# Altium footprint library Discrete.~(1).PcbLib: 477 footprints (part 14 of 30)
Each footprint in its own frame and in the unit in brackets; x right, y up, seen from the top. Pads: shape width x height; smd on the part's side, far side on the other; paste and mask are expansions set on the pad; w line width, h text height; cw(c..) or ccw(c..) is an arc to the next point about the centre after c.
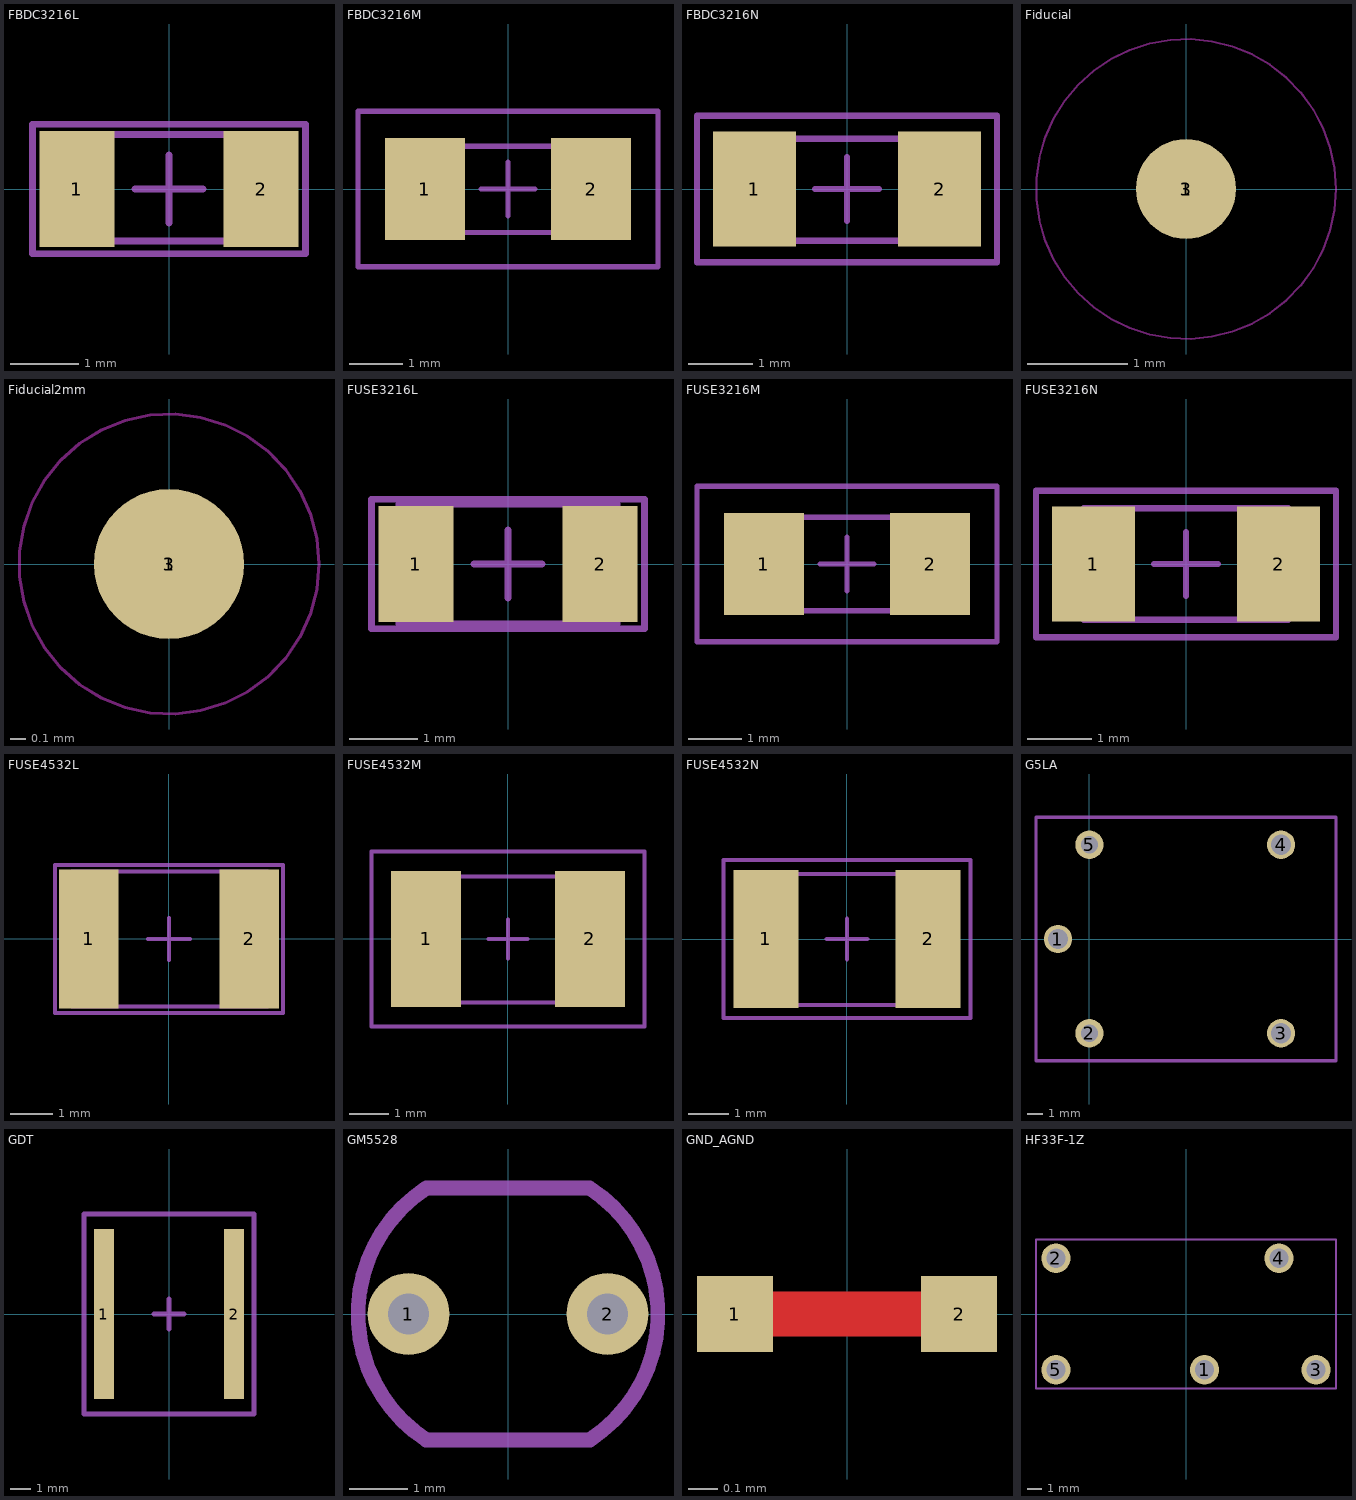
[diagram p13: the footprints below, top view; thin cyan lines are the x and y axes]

## FBDC3216L [mm] "Ferrite Bead, Body 3.2x1.6mm, IPC High Density"
height 0.71
pads (2):
  rect 1.1x1.7 smd: 1(-1.35,0) 2(1.35,0)
Mechanical 13:
  lines w0.1: -1.6,-0.762 -1.6,0.8 1.6,0.8 1.6,-0.762 -1.6,-0.762
Mechanical 15:
  lines w0.1: -0.5,0 0.5,0 ; 0,-0.5 0,0.5 ; -2,-0.95 -2,0.95 2,0.95 2,-0.95 -2,-0.95
3D body "User Library-ind_1206.STEP": height 1.1, standoff 0, extent -1.6,-0.8 1.6,0.8

## FBDC3216M [mm] "Ferrite Bead, Body 3.2x1.6mm, IPC Low Density"
height 0.71
pads (2):
  rect 1.5x1.9 smd: 1(-1.55,0) 2(1.55,0)
Mechanical 13:
  lines w0.1: -1.6,-0.813 -1.6,0.8 -1.587,0.799 0.837,0.799 1.601,0.799 1.601,-0.813 -1.6,-0.813
Mechanical 15:
  lines w0.1: -0.5,0 0.5,0 ; 0,-0.5 0,0.5 ; -2.8,-1.45 -2.8,1.45 2.8,1.45 2.8,-1.45 -2.8,-1.45
3D body "User Library-ind_1206.STEP": height 1.1, standoff 0, extent -1.6,-0.8 1.6,0.8

## FBDC3216N [mm] "Ferrite Bead, Body 3.2x1.6mm, IPC Medium Density"
height 0.71
pads (2):
  rect 1.3x1.8 smd: 1(-1.45,0) 2(1.45,0)
Mechanical 13:
  lines w0.1: -1.6,-0.813 -1.6,0.787 1.6,0.787 1.6,-0.813 -1.6,-0.813
Mechanical 15:
  lines w0.1: -0.5,0 0.5,0 ; 0,-0.5 0,0.5 ; -2.35,-1.15 -2.35,1.15 2.35,1.15 2.35,-1.15 -2.35,-1.15
3D body "User Library-ind_1206.STEP": height 1.1, standoff 0, extent -1.6,-0.8 1.6,0.8

## Fiducial [mm]
pads (2):
  round 1 smd: 1(0,0)
  round 3 on Top Solder: 3(0,0)
Top Layer keep-out:
  circle w0.02: c0,0 r1.5

## Fiducial2mm [mm]
pads (2):
  round 1 smd: 1(0,0)
  round 2 on Top Solder: 3(0,0)
Top Layer keep-out:
  circle w0.02: c0,0 r1

## FUSE3216L [mm] "Fuse, Body 3.2x1.6mm, IPC High Density"
height 0.71
pads (2):
  rect 1.1x1.7 smd: 1(-1.35,0) 2(1.35,0)
Mechanical 13:
  lines w0.1: -1.601,-0.875 1.601,-0.875 1.601,0.875 -1.601,0.875 -1.601,-0.875
Mechanical 15:
  lines w0.1: -0.5,0 0.5,0 ; 0,-0.5 0,0.5 ; -2,-0.95 2,-0.95 2,0.95 -2,0.95 -2,-0.95
3D body "User Library-nona SMD075F.STEP": height 0.56, standoff 0, extent -1.601,-0.826 1.601,0.826

## FUSE3216M [mm] "Fuse, Body 3.2x1.6mm, IPC Low Density"
height 0.71
pads (2):
  rect 1.5x1.9 smd: 1(-1.55,0) 2(1.55,0)
Mechanical 13:
  lines w0.1: -1.601,-0.875 -1.601,0.875 1.601,0.875 1.601,-0.875 -1.601,-0.875
Mechanical 15:
  lines w0.1: -0.5,0 0.5,0 ; 0,-0.5 0,0.5 ; -2.8,-1.45 -2.8,1.45 2.8,1.45 2.8,-1.45 -2.8,-1.45
3D body "User Library-nona SMD075F.STEP": height 0.56, standoff 0, extent -1.601,-0.826 1.601,0.826

## FUSE3216N [mm] "Fuse, Body 3.2x1.6mm, IPC Medium Density"
height 0.71
pads (2):
  rect 1.3x1.8 smd: 1(-1.45,0) 2(1.45,0)
Mechanical 13:
  lines w0.1: -1.601,-0.875 -1.601,0.875 1.601,0.875 1.601,-0.875 -1.601,-0.875
Mechanical 15:
  lines w0.1: -0.5,0 0.5,0 ; 0,-0.5 0,0.5 ; -2.35,-1.15 -2.35,1.15 2.35,1.15 2.35,-1.15 -2.35,-1.15
3D body "User Library-nona SMD075F.STEP": height 0.56, standoff 0, extent -1.601,-0.826 1.601,0.826

## FUSE4532L [mm]
height 0.71
pads (2):
  rect 1.4x3.3 smd: 1(-1.9,0) 2(1.9,0)
Mechanical 13:
  lines w0.1: -2.298,-1.598 -2.298,1.597 2.337,1.597 2.337,-1.598 -2.298,-1.598
Mechanical 15:
  lines w0.1: -0.5,0 0.5,0 ; 0,-0.5 0,0.5 ; -2.7,-1.75 -2.7,1.75 2.7,1.75 2.7,-1.75 -2.7,-1.75
3D body "FU 01812.STEP": height 0.87, standoff 0, extent -2.3,-1.61 2.3,1.61

## FUSE4532M [mm]
height 0.71
pads (2):
  rect 1.8x3.5 smd: 1(-2.1,0) 2(2.1,0)
Mechanical 13:
  lines w0.1: -2.311,-1.626 -2.311,1.6 2.311,1.6 2.311,-1.626 -2.311,-1.626
Mechanical 15:
  lines w0.1: -0.5,0 0.5,0 ; 0,-0.5 0,0.5 ; -3.5,-2.25 -3.5,2.25 3.5,2.25 3.5,-2.25 -3.5,-2.25
3D body "FU 01812.STEP": height 0.87, standoff 0, extent -2.3,-1.61 2.3,1.61

## FUSE4532N [mm]
height 0.71
pads (2):
  rect 1.6x3.4 smd: 1(-2,0) 2(2,0)
Mechanical 13:
  lines w0.1: -2.311,-1.626 2.311,-1.626 2.311,1.6 -2.311,1.6 -2.311,-1.626
Mechanical 15:
  lines w0.1: -0.5,0 0.5,0 ; 0,-0.5 0,0.5 ; -3.05,-1.95 3.05,-1.95 3.05,1.95 -3.05,1.95 -3.05,-1.95
3D body "FU 01812.STEP": height 0.87, standoff 0, extent -2.3,-1.61 2.3,1.61

## G5LA [mm]
pads (5):
  round 1.8 hole 1.3: 1(-2,0) 3(12.2,-6) 4(12.2,6)
  round 1.8 hole 1.1: 2(0,-6) 5(0,6)
Mechanical 13:
  lines w0.203: -3.4,-7.75 -3.4,7.75 15.7,7.75 15.7,-7.75 -3.4,-7.75
3D body "User Library-$RI3BFQW.STEP": height 15.8, standoff -2.9, extent -3.296,-7.9 16.504,7.9

## GDT [mm]
pads (2):
  rect 1x8.5 smd: 1(-3.25,0) 2(3.25,0)
Mechanical 15:
  lines w0.254: -0.75,0 0.75,0 ; 0,-0.75 0,0.75 ; -4.25,-5 -4.25,5 4.25,5 4.25,-5 -4.25,-5
3D body: height 7.97, standoff 0, extent -3.25,-3.992 -2.75,3.992
3D body: height 7.97, standoff 0, extent 2.75,-3.992 3.25,3.992
3D body: height 7.97, standoff 0, extent -2.75,-3.992 2.75,3.992

## GM5528 [mm]
pads (2):
  round 1.4 hole 0.7: 1(-1.7,0) 2(1.7,0)
Mechanical 13:
  lines w0.254: -1.4,-2.15 1.4,-2.15 ; -1.397,2.146 ccw(c0,0) -1.391,-2.15 ; -1.391,2.15 1.391,2.15 cw(c0,0) 1.397,-2.146
3D body: height 2.4, standoff 0, extent -2.6,-2.2 2.5,2.2

## GND_AGND [mil]
pads (2):
  rect 10x10 smd mask+0: 1(-14.76,0) 2(14.76,0)
Top Layer:
  lines w5.98: -14.76,0 -7.38,0 7.38,0 14.76,0

## HF33F-1Z [mm]
pads (5):
  round 2 hole 1.3: 1(1.27,-3.81) 2(-8.89,3.81) 3(8.89,-3.81) 4(6.35,3.81) 5(-8.89,-3.81)
Mechanical 13:
  lines w0.127: -10.25,-5.1 10.25,-5.1 ; -10.25,-5.08 -10.25,5.08 ; -10.25,5.1 10.25,5.1 ; 10.25,-5.08 10.25,5.08
3D body: height 15.7, standoff 0, extent -10.25,-5.08 10.25,5.08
